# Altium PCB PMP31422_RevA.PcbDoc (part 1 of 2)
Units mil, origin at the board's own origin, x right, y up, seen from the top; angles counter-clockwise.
Board outline 5850 x 1977.34 mil, 2 copper layers (Top Layer, Bottom Layer), stack 62 mil thick; 70 components, 36 nets, 149 pads, 18 vias.
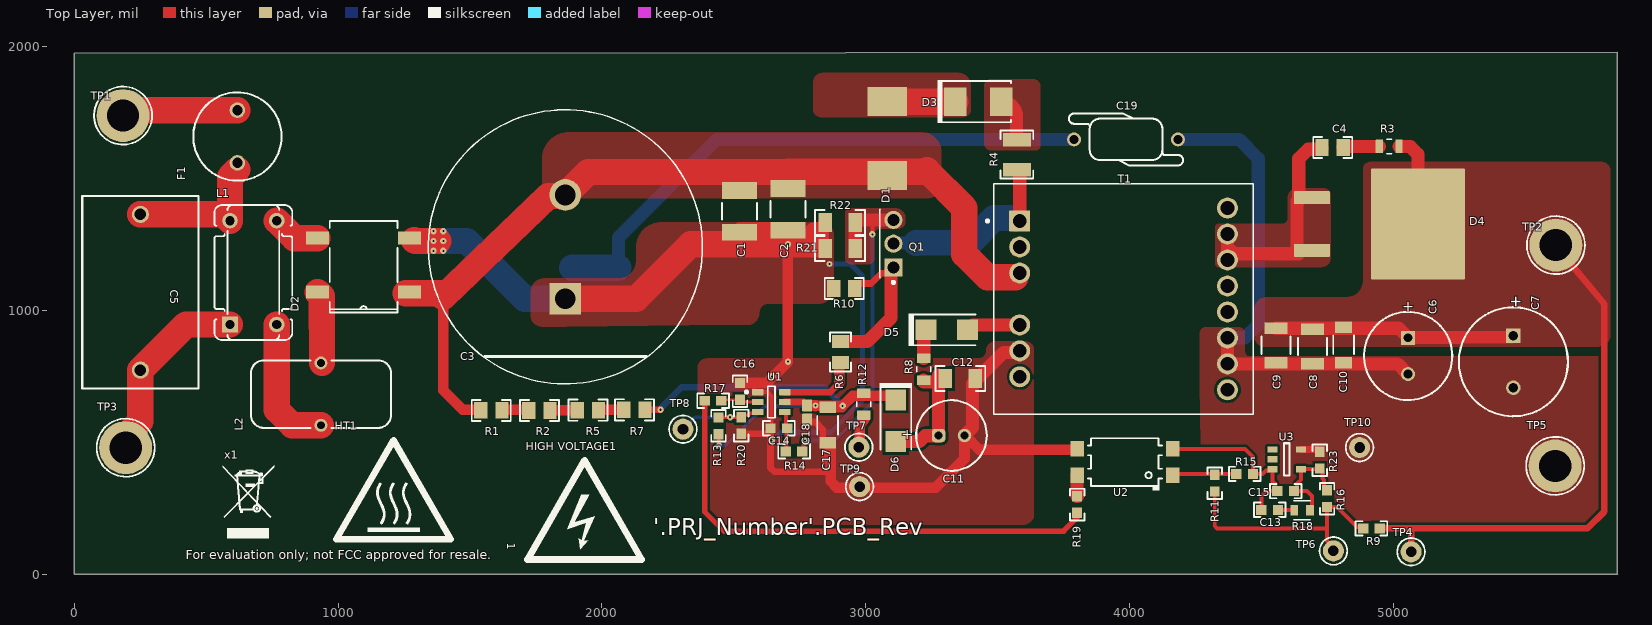
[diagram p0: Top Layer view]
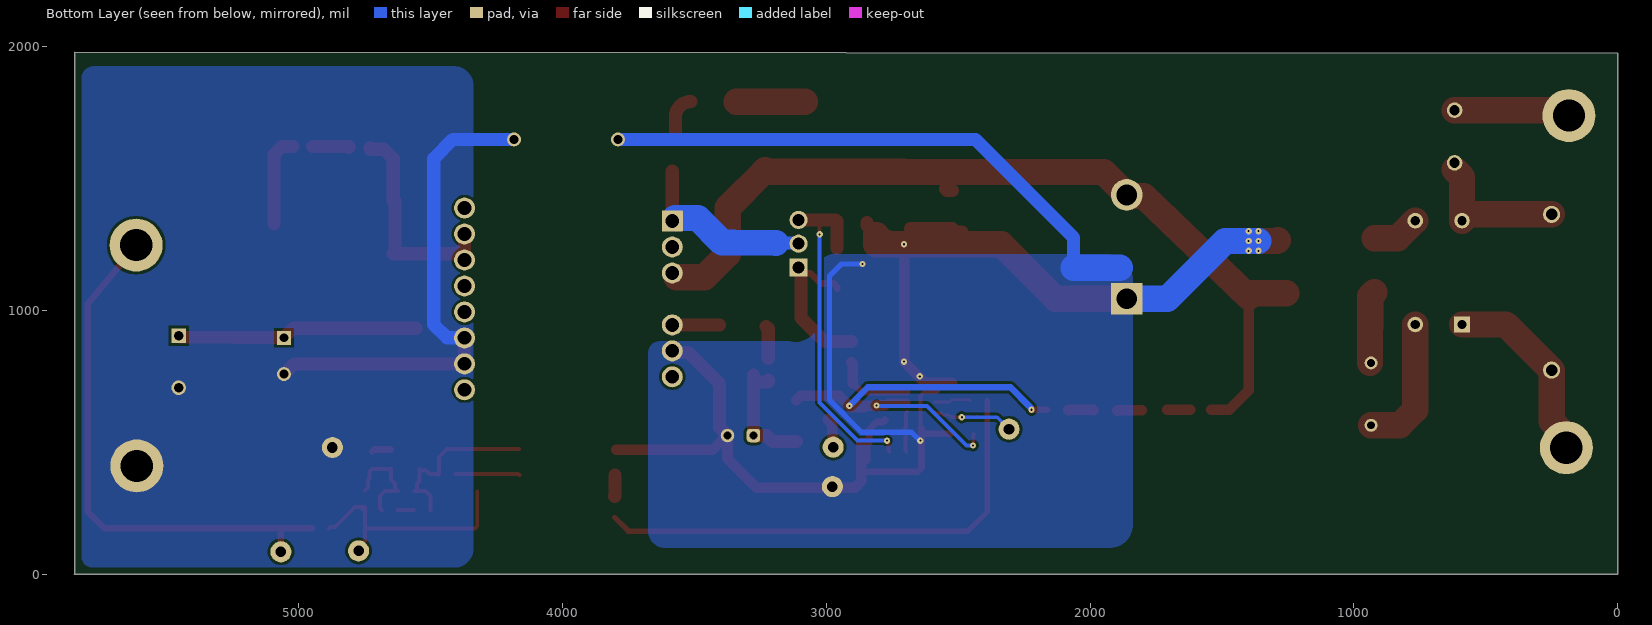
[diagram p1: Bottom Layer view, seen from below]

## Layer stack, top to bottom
Top Solder: solder mask 0.4, Solder Resist, Dk 3.5
Top Layer: signal copper 1.4
Dielectric1: core 59.2, FR-4 High Tg, Dk 4.8
Bottom Layer: signal copper 1.4
Bottom Solder: solder mask 0.4, Solder Resist, Dk 3.5

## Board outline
0,0 5850,0 5847.86,0.02 5847.86,1977.34 0,1975

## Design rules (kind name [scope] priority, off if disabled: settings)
AcuteAngle [All] p1: minimum=4.50000000000000E+0001 checktracksonly=FALSE
AssemblyTestPointUsage [All] p1: valid=2
BoardOutlineClearance BoardOutlineClearance_MountingHoles [OnCopper and InComponentClass('Mounting Holes')] p1: gap=39.37 ignorepadtopadclearanceinfootprint=FALSE
BoardOutlineClearance BoardOutlineClearance_Poly [OnCopper and IsPoly] p2: gap=25 ignorepadtopadclearanceinfootprint=FALSE
BoardOutlineClearance [OnCopper and Not InComponentClass('Logo') and not InComponentClass('FiducialMark') and not InRegion(1000,500,4000,800) and not InPoly] p3: gap=35 ignorepadtopadclearanceinfootprint=FALSE
Clearance Clearance_Keepouts [((IsTrack Or IsArc) And Not InPoly) And IsFree and IsKeepOut vs ((IsTrack Or IsArc) And Not InPoly) And IsFree and IsKeepOut] p1: gap=0 ignorepadtopadclearanceinfootprint=FALSE
Clearance Clearance_Poly [InPolygon] p2: gap=10 ignorepadtopadclearanceinfootprint=TRUE
Clearance Clearance_FiducialMark [IsKeepOut and InComponentClass('FiducialMark') vs IsPad and InComponentClass('FiducialMark')] p3: gap=0 ignorepadtopadclearanceinfootprint=FALSE
Clearance [All] p4: gap=7.87 ignorepadtopadclearanceinfootprint=TRUE
ComponentClearance ComponentClearance_MountingHoles_FiducialMarks [InComponentClass('Mounting Holes') vs InComponentClass('FiducialMark')] p1: gap=50 collisioncheckmode=3 verticalgap=10 showdistances=FALSE
ComponentClearance ComponentClearance_Shunt [InComponentClass('Header') vs InComponentClass('Shunt')] p2: gap=0 collisioncheckmode=3 verticalgap=0 showdistances=FALSE
ComponentClearance ComponentClearance_Logo [InComponentClass('Logo')] p3: gap=30 collisioncheckmode=3 verticalgap=10 showdistances=FALSE
ComponentClearance ComponentClearance_ScrewToNut [(HasFootprint('NY PMS 440 0025 PH')) vs (HasFootprint('Keystone_1902C'))] p4: gap=5 collisioncheckmode=3 verticalgap=10 showdistances=FALSE
ComponentClearance ComponentClearance_MountingHoles [InComponentClass('Mounting Holes')] p5: gap=100 collisioncheckmode=3 verticalgap=100000 showdistances=FALSE
ComponentClearance ComponentClearance_SmallPassives [HasFootprint('0201*') or HasFootprint('0402*') or HasFootprint('0508') or HasFootprint('0603*') or HasFootprint('0612') or HasFootprint('0805*') or HasFootprint('0815*') or HasFootprint('0830*') or HasFootprint('1206*') or HasFootprint('1210*') or HasFootprint('1808*') or HasFootprint('1812*') or HasFootprint('1825*') or HasFootprint('2010*') or HasFootprint('2220*') or HasFootprint('2225*') or HasFootprint('2512*') or HasFootprint('2728*') or HasFootprint('3518*') vs HasFootprint('0201*') or HasFootprint('0402*') or HasFootprint('0508') or HasFootprint('0603*') or HasFootprint('0612') or HasFootprint('0805*') or HasFootprint('0815*') or HasFootprint('0830*') or HasFootprint('1206*') or HasFootprint('1210*') or HasFootprint('1808*') or HasFootprint('1812*') or HasFootprint('1825*') or HasFootprint('2010*') or HasFootprint('2220*') or HasFootprint('2225*') or HasFootprint('2512*') or HasFootprint('2728*') or HasFootprint('3518*')] p6: gap=14.96 collisioncheckmode=3 verticalgap=10 showdistances=FALSE
ComponentClearance ComponentClearance_THtoSMT [IsThruComponent vs IsSMTComponent] p7: gap=30 collisioncheckmode=3 verticalgap=30 showdistances=FALSE
ComponentClearance ComponentClearance_THtoTH [IsThruComponent vs IsThruComponent] p8: gap=20 collisioncheckmode=3 verticalgap=30 showdistances=FALSE
ComponentClearance [All] p9: gap=20 collisioncheckmode=3 verticalgap=10 showdistances=FALSE
DiffPairsRouting [All] p1: maxlimit=100 minlimit=10 mostfreqgap=10 toplayer_minwidth=15 toplayer_maxwidth=15 toplayer_prefwidth=15 bottomlayer_minwidth=15 bottomlayer_maxwidth=15 bottomlayer_prefwidth=15 maxuncoupledlength=1000
FabricationTestPointUsage TestPointUsage [All] p1: valid=2 allowmultiple=FALSE
FabricationTestpoint Testpoint [All] p1: side=3 testpointundercomponent=TRUE minsize=40 maxsize=100 preferedsize=60 minholesize=0 maxholesize=40 preferedholesize=32 testpointgrid=1 allowsidetop=TRUE allowsidebottom=TRUE usegrid=TRUE gridtolerance=0.01
FanoutControl Fanout_LCC [IsLCC] p1: bgadir=Out bgaviamode=Centered fanoutstyle=Auto fanoutdirection=Alternating viagrid=1 // Fanout_LCC (Default Rule)
FanoutControl Fanout_BGA [IsBGA] p2: bgadir=Out bgaviamode=Centered fanoutstyle=Auto fanoutdirection=Alternating viagrid=1 // Fanout_BGA (Default Rule)
FanoutControl Fanout_Default [All] p4: bgadir=Out bgaviamode=Centered fanoutstyle=Auto fanoutdirection=Alternating viagrid=1 // Fanout_Default (Default Rule)
FanoutControl Fanout_Small [(CompPinCount < 5)] p5: bgadir=Out bgaviamode=Centered fanoutstyle=Auto fanoutdirection=OutThenIn viagrid=1 // Fanout_Small (Default Rule)
Height [All] p1: minheight=0 maxheight=1500 prefheight=500
HoleSize [All] p1: absolutevalues=TRUE maxlimit=251 minlimit=7.87 maxpercent=80.000 minpercent=20.000
MinimumAnnularRing MinimumAnnularRing_ThermalPadVias [IsVia and InAnyComponent] p1: minimumring=5.91
MinimumAnnularRing [All] p2: minimumring=7.87
MinimumSolderMaskSliver MinimumSolderMaskSliver_Logo [InComponentClass('Logo') vs InComponentClass('Logo')] p1: minsoldermaskwidth=0.7
MinimumSolderMaskSliver [All] p2: minsoldermaskwidth=3.94
PlaneConnect [All] p1: planeconnectstyle=Relief reliefexpansion=10 reliefentries=4 reliefconductorwidth=10 reliefairgap=10
PolygonConnect [All] p1: connectstyle=Direct reliefconductorwidth=10 reliefentries=4 polygonreliefangle="90 Angle" airgapwidth=10
RoutingVias ThermalPadVias [IsVia and InAnyComponent] p1: holewidth=7.87 width=19.68 viastyle="Through Hole" minholewidth=7.87 minwidth=19.68 maxholewidth=12.99 maxwidth=23.62
RoutingVias [All] p2: holewidth=16 width=34 viastyle="Through Hole" minholewidth=7.87 minwidth=24 maxholewidth=40 maxwidth=65
SilkToBoardRegionClearance [Not ((IsComment or IsDesignator) And (Hide <> 'False')) and not InRegion(1000,500,4000,800)] p1:
SilkToSilkClearance SilkToSilkClearance_Pb-FreeLogo [(HasFootprint('Pb-Free_Overlay_Medium') OR HasFootprint('Pb-Free_Overlay_Small')) vs (HasFootprint('Pb-Free_Overlay_Medium') OR HasFootprint('Pb-Free_Overlay_Small'))] p1 off: silktosilkclearance=0
SilkToSilkClearance [All] p2 off: silktosilkclearance=3.94
SilkToSolderMaskClearance SilkToComponentPadClearance [(IsPad or IsFill or IsRegion) and InAnycomponent] p1 off: minsilkscreentomaskgap=5 clearancetoexposedcopper=TRUE
SilkToSolderMaskClearance "Silk to Solder Mask Opening" [All] p2 off: minsilkscreentomaskgap=3.94 clearancetoexposedcopper=FALSE
SolderMaskExpansion [All] p1: expansion=1.97 istentingtop=FALSE
UnRoutedNet [All] p1: checkbadconnections=TRUE
Width [All] p1: maxlimit=100 minlimit=6 preferedwidth=10 checkconnectedcopper=TRUE
13 further rules are at their usual default settings.

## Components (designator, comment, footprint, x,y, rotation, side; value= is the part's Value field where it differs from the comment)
1 "FCC disclaimer" FCC_disclaimer 1049.65,56.66 r0 top
C1 "1812Y5000474KXTWS2" 1812_254 2521.46,1375.09 r270 top value=0.47uF
C2 "1812Y5000474KXTWS2" 1812_254 2704.98,1382.55 r270 top value=0.47uF
C3 "B43541B8476M080" FP-B43541B8476M080_RADIAL-MFG 1861.1,1240.23 r90 top value=47µF
C4 "GRM2165C2A102JA01D" 0805_HV 4770.03,1617 r180 top value=DNP
C5 "R474I310050A1K" Kemet_1800x1100x1900 250.24,1068.16 r270 top value=0.1uF
C6 "APSG160ELL471MH08S" PSG_800x800 5055.86,826.67 r270 top value=470uF
C7 "16SEPC470M+T" SEPC_F13 5454.97,804.61 r270 top value=470uF
C8 "C3225X7R1C226K250AC" 1210_280 4693.07,862.64 r270 top value=22uF
C9 "C3225X7R1C226K250AC" 1210_280 4555.57,866.49 r270 top value=22uF
C10 "C3216X7R1C106M160AC" 1206_180 4811.17,868.58 r270 top value=10uF
C11 "860040573004" WCAP-ATUL_D6.3H11 3325.01,525.09 r180 top
C12 "GMK316AB7106KL" 1206 3358.13,740.92 r180 top value=10uF
C13 "DNPC0603C220J5GACTU" 0603 4531.38,243.36 r0 top value=DNP
C14 "C0603C220J5GACTU" 0603 2670.46,552.48 r180 top value=22pF
C15 "GRM188R71H103KA01D" 0603 4591.75,314.18 r0 top value=0.01uF
C16 "GRM188R71H102KA01D" 0603 2523.18,692.73 r90 top value=1000pF
C17 "GRM31CR71H475KA12L" 1206_180 2855.32,564.56 r270 top value=4.7uF
C18 "C0603R104K5RAC" FP-C0603R104K5RAC_0603-IPC_B 2777.74,612.5 r270 top
C19 "C901U102MYVDBA7317" C901_B 3986.6,1647.53 r180 top value=1000pF
D1 "SMCJ154CA-TR" SMC_Bi 3081.3,1650.77 r270 top value=154V
D2 "DF08SA" DF-S 1096.11,1171.08 r180 top value=800V
D3 "MURS160-13-F" SMB 3425.98,1790.97 r0 top value=600V
D4 "STPS8H100G-TR" DDPAK 4937.73,1326.93 r0 top value=100V
D5 "B1100-13-F" SMA 3306.68,925.68 r0 top value=100V
D6 "B1100-13-F" SMA 3113.93,580.85 r270 top value=100V
F1 "DNP" FUSE_372 618.02,1658.38 r90 top
"HIGH VOLTAGE1" "DANGER HIGH VOLTAGE" IEC_HighVoltage_Medium 1934.1,230.43 r0 top
HT1 "CAUTION HOT SURFACE" IEC_HotSurface_Medium 1209.94,319.49 r0 top
L1 "744821150" WE-CMB_XS 678.33,1142.82 r90 top value=5mH
L2 "7447031" WE-FI_1350x700 934.52,682 r90 top value=140uH
Q1 "IPSA70R2K0CE" FP-IPSA70R2K0CE_TO251-3-MFG 3099.72,1252.33 r180 top
R1 "CRCW080510M0JNEA" 0805_HV 1580.33,620.15 r180 top value=10Meg
R2 "CRCW080510M0JNEA" 0805_HV 1762.63,620.03 r180 top value=10Meg
R3 "TNPW0805100RBYEN" FP-TNPW0805100RBYEN_0805-MFG 4984.2,1621.14 r0 top value=DNP
R4 "CRCW121010R0FKEAHP" 1210 3573.02,1590.07 r90 top value=10.0
R5 "CRCW080510M0JNEA" 0805_HV 1946.51,621.32 r180 top value=10Meg
R6 "CRCW080510R0FKEA" 0805_HV 2904.09,841.95 r90 top value=10.0
R7 "CRCW080510M0JNEA" 0805_HV 2122.77,622.5 r180 top value=10Meg
R8 "RMCF0805ZT0R00" FP-RMCF0805ZT0R00_0805-MFG 3219.37,776 r90 top
R9 "CRCW060349R9FKEA" 0603 4916.7,172.82 r0 top value=49.9
R10 "CRCW080510K0FKEA" 0805_HV 2918.41,1082.52 r0 top value=10.0k
R11 "RC0603FR-076K49L" 0603 4322.88,344.38 r90 top value=6.49k
R12 "RMCF0805ZT0R00" FP-RMCF0805ZT0R00_0805-MFG 2992.26,643.88 r90 top
R13 "CRCW0603200KFKEA" 0603 2441.65,562.02 r270 top value=200k
R14 "RMCF0603ZT0R00" 0603 2728.14,465.04 r180 top value=0
R15 "RCG060310K0FKEA" 0603 4436.32,379.35 r180 top value=10.0k
R16 "CRCW06031M00FKEA" 0603 4748.71,285.44 r270 top value=1.00Meg
R17 "RMCF0603ZT0R00" 0603 2421.11,656.71 r180 top value=0
R18 "DNP" FP-CRCW06030000Z0EAHP_0603-MFG 4654.19,241.57 r0 top
R19 "RMCF0603ZT0R00" 0603 3801.39,263.28 r270 top value=0
R20 "CRCW060368K1FKEA" 0603 2528.08,562.7 r90 top value=68.1k
R21 "TBD" 1206 2902.58,1234.09 r0 top
R22 "ERJ-8RQF1R8V" 1206 2902.54,1332.97 r0 top value=1.80
R23 "CRCW0603115KFKEA" 0603 4720.83,431.5 r90 top value=115k
T1 "750372566r00" FP-750372566r00_PTH14-MFG 3977.31,1042.78 r0 top
TP1 "1503-2" Keystone1503-2 184.35,1737.92 r90 top
TP2 "1503-2" Keystone1503-2 5615.95,1246.72 r90 top
TP3 "1503-2" Keystone1503-2 194.5,478.89 r0 top
TP4 "5000" Keystone5000 5067.09,84.27 r90 top
TP5 "1503-2" Keystone1503-2 5613.53,410.04 r0 top
TP6 "5000" Keystone5000 4772.83,87.67 r90 top
TP7 "5000" Keystone5000 2973.59,480.76 r90 top
TP8 "5000" Keystone5000 2307,548.99 r90 top
TP9 "5002" Keystone5002 2976.44,331.41 r90 top
TP10 "5001" Keystone5001 4871.84,479.56 r90 top
U1 "UCC287508DBVR" DBV0006A-MFG 2641.97,652.07 r0 top
U2 "FOD817ASD" N04C 3982.37,424.56 r180 top
U3 "TLV431AIDBVT" DBV0005A_N 4595.95,434.74 r0 top
x1 "WEEE logo" WEEE_Minimum 657.54,307.2 r0 top

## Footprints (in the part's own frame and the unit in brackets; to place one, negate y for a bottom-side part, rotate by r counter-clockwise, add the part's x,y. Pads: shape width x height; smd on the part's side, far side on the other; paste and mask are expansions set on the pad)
0603 [mm] "0603 from SM-752 data"
  rect 1x0.95 smd: 1(-0.8,0) 2(0.8,0)
  silkscreen extent -1.52,-0.69 1.52,0.69, body extent -0.87,-0.47 0.87,0.47, height 1
0805_HV [mil] "0805 with 30mil clearance between pads"
  rect 50x63 smd: 1(-40,0) 2(40,0)
  silkscreen extent -74,-40 74,40, body extent -43,-29 43,29, height 57
1206 [mm] "1206 from SM-752 data"
  rect 1.3x1.85 smd: 1(-1.45,0) 2(1.45,0)
  silkscreen extent -2.4,-1.21 2.4,1.21, body extent -1.7,-0.9 1.7,0.9, height 1.35
1206_180 [mm] "1206_180"
  rect 1.1x1.6 smd: 1(-1.7,0) 2(1.7,0)
  silkscreen extent -0.9,-1 0.9,1, body extent -1.75,-0.95 1.75,0.95, height 1.8
1210 [mm] "1210 from SM-752 data"
  rect 1.3x2.7 smd: 1(-1.45,0) 2(1.45,0)
  silkscreen extent -2.32,-1.57 2.32,1.57, body extent -1.7,-1.35 1.7,1.35, height 1.35
1210_280 [mm] "SMD, 2-Leads, Body 3.6x2.8mm, Height 2.8mm"
  rect 1.1x2.2 smd: 1(-1.65,0) 2(1.65,0)
  silkscreen extent -0.84,-1.4 0.84,1.4, body extent -1.8,-1.4 1.8,1.4, height 2.8
1812_254 [mm] "SMD, 2-Leads, Body 4.8x3.4mm"
  rect 1.6x3.4 smd: 1(-2,0) 2(2,0)
  silkscreen extent -0.8,-1.7 0.8,1.7, body extent -2.4,-1.7 2.4,1.7, height 2.54
C901_B [mm] "TH, 2-Leads, Body 7x5mm, Pin Spacing 10mm"
  round 1.35 hole 0.85: 1(-5,0) 2(5,0)
  silkscreen extent -5.5,-2.5 5.5,2.5, body extent -5.5,-2.5 5.5,2.5, height 11
DBV0005A_N [mm] "SOT23, 5-Leads, Body 2.9x1.6mm, Pitch 0.95mm, Lead Span 2.8mm, IPC Medium Density"
  rrect17% 1x0.6 smd: 1(-1.375,0.95) 2(-1.375,0) 3(-1.375,-0.95) 4(1.375,-0.95) 5(1.375,0.95)
  silkscreen extent -0.25,-1.55 0.25,1.55, body extent -1.42,-1.46 1.42,1.46, height 1.09
DBV0006A-MFG [mm]
  rrect17% 1.1x0.6 smd paste+0 mask+0: 1(-1.3,0.95) 2(-1.3,0) 3(-1.3,-0.95) 4(1.3,-0.95) 5(1.3,0) 6(1.3,0.95)
  silkscreen extent -2.52,-1.53 0.35,1.53, body extent -1.95,-1.78 1.95,1.78, height 0.25
DDPAK [mil] "D2-PAK, 3-Pads, Body 9.7x10.4mm (max), TO-263AB, using Vishay Silionix recommended pad sizes"
  rrect8% 135x49.49 smd: 1(-246.06,100) 3(-246.06,-100)
  rrect1% 355x420 smd paste-181.1: 2(155.51,0)
  body extent -295,-202 324,202, height 180
DF-S [mil] "Diodes Inc. recommended land pattern per ap02001.pdf rev 30"
  rect 88x49 smd: 1(-174.5,102.36) 2(-174.5,-102.36) 3(174.5,-102.36) 4(174.5,102.36)
  silkscreen extent -128,-168 128,180, body extent -205,-168 205,168, height 108
FCC_disclaimer [mil]
FP-750372566r00_PTH14-MFG [mm] "Recommended Land Pattern"
  rrect5% 2.02x2.02 hole 1.32 paste-2539.97 mask+0: 1(-10,7.5)
  round 2.02 hole 1.32 paste-2539.97 mask+0: 2(-10,5) 3(-10,2.5) 4(-10,-2.5) 5(-10,-5) 6(-10,-7.5) 7(10,-8.75) 8(10,-6.25) 9(10,-3.75) 10(10,-1.25) 11(10,1.25) 12(10,3.75) 13(10,6.25) 14(10,8.75)
  silkscreen extent -13.22,-11.1 12.5,11.1, body extent -12.5,-11.1 12.5,11.1, height 16
FP-B43541B8476M080_RADIAL-MFG [mm] "Recommended Land Pattern"
  rrect3% 3.05x3.05 hole 2 paste-2539.97 mask+0: 1(-5,0)
  round 3.05 hole 2 paste-2539.97 mask+0: 2(5,0)
  silkscreen extent -13.2,-13.2 13.2,13.2, body extent -12.5,-12.5 12.5,12.5, height 27.2
FP-C0603R104K5RAC_0603-IPC_B [mil]
  rrect10% 44.33x37.73 smd paste+0 mask+0: 1(-26.6,0) 2(26.6,0)
  body extent -59,-29 59,29, height 10
FP-CRCW06030000Z0EAHP_0603-MFG [mm]
  rrect13% 0.75x1 smd paste+0 mask+0: 1(-0.75,0) 2(0.75,0)
  silkscreen extent -0.8,-0.9 0.8,0.9, body extent -1.22,-0.6 1.22,0.6, height 0.25
FP-IPSA70R2K0CE_TO251-3-MFG [mm] "Recommended Land Pattern"
  rrect6% 1.75x1.75 hole 1.15 paste-2539.97 mask+0: 1(-0.128,2.286)
  round 1.75 hole 1.15 paste-2539.97 mask+0: 2(-0.128,0) 3(-0.128,-2.286)
  silkscreen extent -0.25,-3.3 1.19,3.85, body extent -1.15,-3.3 1.15,3.3, height 9
FP-RMCF0805ZT0R00_0805-MFG [mm]
  rrect11% 0.9x1.3 smd paste+0 mask+0: 1(-1.05,0) 2(1.05,0)
  silkscreen extent -0.23,-0.67 0.23,0.67, body extent -1.6,-0.77 1.6,0.77, height 0.25
FP-TNPW0805100RBYEN_0805-MFG [mm]
  rrect14% 0.7x1.3 smd paste+0 mask+0: 1(-0.95,0) 2(0.95,0)
  silkscreen extent -0.23,-0.7 0.23,0.7, body extent -1.4,-0.8 1.4,0.8, height 0.25
FUSE_372 [mm] "LITTELFUSE"
  round 1.5 hole 1: 1(-2.54,0) 2(2.54,0)
  silkscreen extent -4.25,-4.25 4.25,4.25, body extent -4.25,-4.25 4.25,4.25, height 8
IEC_HighVoltage_Medium [mil]
  silkscreen extent -217,-176 217,200
IEC_HotSurface_Medium [mil]
  silkscreen extent -217,-188 217,188
Kemet_1800x1100x1900 [mm] "TH, 2-Leads, Body 18x11mm, Pin Spacing 15mm"
  round 1.65 hole 1.1: 1(-7.5,0) 2(7.5,0)
  silkscreen extent -9.25,-5.6 9.25,5.6, body extent -9.25,-5.6 9.25,5.6, height 19.1
Keystone1503-2 [mm] "Double Turret"
  round 5.1 hole 3.1: 1(0,0)
  silkscreen extent -2.79,-2.79 2.79,2.79, body extent -2.4,-2.4 2.38,2.4, height 9.22
Keystone5000 [mil] "For Keystone 500x miniature loop terminals"
  round 80 hole 40: 1(0,0)
  silkscreen extent -52,-52 52,52, body extent -49,-49 49,49, height 182
Keystone5001 [mil] "For Keystone 500x miniature loop terminals"
  round 80 hole 40: 1(0,0)
  silkscreen extent -52,-52 52,52, body extent -49,-49 49,49, height 182
Keystone5002 [mil] "For Keystone 500x miniature loop terminals"
  round 80 hole 40: 1(0,0)
  silkscreen extent -52,-52 52,52, body extent -49,-49 49,49, height 182
N04C [mm] "FAIRCHILD"
  rect 1.3x1.5 smd mask+0.065: 1(-4.587,1.27) 2(-4.612,-1.27) 3(4.588,-1.27) 4(4.613,1.27)
  silkscreen extent -3.56,-2.3 3.56,2.72, body extent -5.08,-2.3 5.08,2.3, height 3.87
PSG_800x800 [mm] "TH, 2-Leads, Dia 8mm, Pin Spacing 3.5mm"
  rect 1.35x1.35 hole 0.85: 1(-1.75,0)
  round 1.35 hole 0.85: 2(1.75,0)
  silkscreen extent -4.25,-4.25 4.25,4.25, body extent -4.25,-4.25 4.25,4.25, height 9.01
SEPC_F13 [mm] "TH, 2-Leads, Dia 10mm, Pin Spacing 5mm"
  rect 1.4x1.4 hole 0.9: 1(-2.5,0)
  round 1.4 hole 0.9: 2(2.5,0)
  silkscreen extent -5.25,-5.25 5.25,5.25, body extent -5.25,-5.25 5.25,5.25, height 13.01
SMA [mm] "Molded Diode, 2-Leads, Body 4.3x2.6mm, IPC Medium Density, based on OnSemi component dimensions and land pattern"
  rect 2x2 smd: 1(-2,0) 2(2,0)
  silkscreen extent -3.66,-1.57 2.79,1.57, body extent -2.6,-1.3 2.6,1.3, height 2.42
SMB [mil] "Molded Diode, 2-Leads, Body 5.4x3.6mm, IPC Medium Density, based on OnSemi component dimensions"
  rect 85x107.99 smd: 1(-87.01,0) 2(87.01,0)
  silkscreen extent -155,-82 125,82, body extent -106,-71 106,71, height 91
SMC_Bi [mil] "SMC, no polarity mark"
  rect 110x150 smd: 1(-140.49,0) 2(140.49,0)
  body extent -156,-116 156,116, height 92
WCAP-ATUL_D6.3H11 [mm] "Aluminum Electrolytic Capacitors, 6.3x11mm"
  rrect50% 1.3x1.3 hole 0.8: 1(1.25,0)
  round 1.3 hole 0.8: 2(-1.25,0)
  silkscreen extent -3.4,-3.4 3.4,3.4, body extent -3.14,-3.15 3.15,3.15, height 11.31
WE-CMB_XS [mm] "WE-CMB Series Size XS"
  rect 1.5x1.5 hole 0.9: 1(-5,2.25)
  round 1.5 hole 0.9: 2(-5,-2.25) 3(5,-2.25) 4(5,2.25)
  silkscreen extent -6.5,-3.75 6.5,3.75, body extent -6.5,-3.75 6.5,3.75, height 16.24
WE-FI_1350x700 [mm] "TH, 2-Leads, Dia 13.5mm"
  round 1.25 hole 0.75: 1(-3,0) 2(3,0)
  silkscreen extent -3.25,-6.75 3.25,6.75, body extent -3.25,-6.75 3.25,6.75, height 13.32
WEEE_Minimum [mil] "WEEElie bin"
  silkscreen extent -95,-172 99,104

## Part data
1: library part CMP-0074847-1, "FCC_disclaimer"
C1 C2: library part CMP-0009298-2, "DNP", Cap_Case=1812, Manufacturer="Knowles Capacitors", Supplier Part Number 1=1608-1155-1-ND, TempCo=X7R, Tolerance_%=10%, Value1=Unknown, Value2=500V
C3: library part CMP-0127623-1, "47 µF 600 V Aluminum Electrolytic Capacitors Radial, Can - Snap-In 2.47Ohm @ 100Hz 5000 Hrs @ 85°C", Digikey Part Number=495-B43541B8476M080-ND, Leakage Current=400uA, Manufacturer=TDK, Mouser Part Number=871-B43541B8476M80, Operating Temperature Range="-25°C to +85°C", Tolerance_%=20%, ValueDisplayed=47uF
C4: library part CMP-0008094-2, "DNP", Cap_Case=0805, Manufacturer=MuRata, TempCo=C0G/NP0, Tolerance_%=5%, Value1=Unknown
C5: library part CMP-0074799-2, "CAP, Film, 0.1 µF, X1 440 VAC, +/- 10%, AEC-Q200 Grade 1, TH", Cap_Case=18x11x19mm, Manufacturer=Kemet, Supplier Part Number 1=399-12721-ND, Tolerance_%=10%, Value2=1000V, ValueDisplayed=0.1µF
C6: library part CMP-0012172-1, "CAP, Aluminum Polymer, 470 uF, 16 V, +/- 20%, 0.016 ohm, TH", Cap_Case=8x8mm, Manufacturer=Chemi-Con, Supplier Part Number 1=565-3620-ND, Tolerance_%=20%, Value1="0.016 ohm", Value2=16V, ValueDisplayed=470uF
C7: library part CMP-0012077-2, "CAP, Aluminum Polymer, 470 uF, 16 V, +/- 20%, 0.01 ohm, TH", Cap_Case=10x13mm, Manufacturer=Panasonic, Supplier Part Number 1=P16383CT-ND, Tolerance_%=20%, Value1="0.01 ohm", Value2=16V, ValueDisplayed=470uF
C8 C9: library part CMP-0009116-1, "CAP, CERM, 22 uF, 16 V, +/- 10%, X7R, 1210", Cap_Case=1210_280, Manufacturer=TDK, Supplier Part Number 1=445-3945-1-ND, TempCo=X7R, Tolerance_%=10%, Value1="0.002582 ohm", Value2=16V, ValueDisplayed=22uF
C10: library part CMP-0082521-1, "CAP, CERM, 10 µF, 16 V,+/- 20%, X7R, 1206", Cap_Case=1206, Manufacturer=TDK, Supplier Part Number 1=445-1601-1-ND, TempCo=X7R, Tolerance_%=20%, Value2=16V, ValueDisplayed=10µF
C11: library part CMP-0116855-1, "WCAP-ATUL Aluminum Electrolytic Capacitor, Radial, THT, D6.3 x H11mm, 100µF, 35V", Capacitance Tolerance=20%, Leakage Current=35uA, Manufacturer="Wurth Elektronik", Operating Temperature Max=105°C, Operating Temperature Min=-40°C, Rated Voltage (DC)=35V, Ripple Current=450mA
C12: library part CMP-0008821-1, "CAP, CERM, 10 uF, 35 V, +/- 10%, X7R, 1206", Cap_Case=1206, Manufacturer="Taiyo Yuden", Supplier Part Number 1=587-3007-1-ND, TempCo=X7R, Tolerance_%=10%, Value1=Unknown, Value2=35V, ValueDisplayed=10uF
C13: library part CMP-0006892-1, "DNP", Cap_Case=0603, Manufacturer=Kemet, Supplier Part Number 1=399-1053-1-ND, TempCo=C0G/NP0, Tolerance_%=5%, Value1=Unknown, Value2=50V
C14: library part CMP-0006892-1, "CAP, CERM, 22 pF, 50 V, +/- 5%, C0G/NP0, 0603", Cap_Case=0603, Manufacturer=Kemet, Supplier Part Number 1=399-1053-1-ND, TempCo=C0G/NP0, Tolerance_%=5%, Value1=Unknown, Value2=50V, ValueDisplayed=22pF
C15: library part CMP-0007433-1, "CAP, CERM, 0.01 uF, 50 V, +/- 10%, X7R, 0603", Cap_Case=0603, Manufacturer=MuRata, Supplier Part Number 1=490-1512-1-ND, TempCo=X7R, Tolerance_%=10%, Value1=Unknown, Value2=50V, ValueDisplayed=0.01uF
C16: library part CMP-0007432-1, "CAP, CERM, 1000 pF, 50 V, +/- 10%, X7R, 0603", Cap_Case=0603, Manufacturer=MuRata, Supplier Part Number 1=490-1494-1-ND, TempCo=X7R, Tolerance_%=10%, Value1=Unknown, Value2=50V, ValueDisplayed=1000pF
C17: library part CMP-0008969-2, "CAP, CERM, 4.7 uF, 50 V, +/- 10%, X7R, 1206", Cap_Case=2220, Manufacturer=MuRata, Supplier Part Number 1=24R6347, TempCo=X7R, Tolerance_%=10%, Value1=Unknown, Value2=50V, ValueDisplayed=4.7uF
C18: library part CMP-0087061-2, "CAP CER 0.1UF 50V X7R 0603", Manufacturer=Kemet, TempCo=15%, Tolerance_%=10%
C19: library part CMP-0009592-2, "CAP, CERM, 1000 pF,  V, +/- 20%, Y5V, D7xT5mm", Cap_Case=7x5mm, Manufacturer=Kemet, Supplier Part Number 1=399-9464-1-ND, TempCo=Y5V, Tolerance_%=20%, Value1=Unknown, Value2=V, ValueDisplayed=1000pF
D1: library part CMP-0085466-1, "Diode, TVS, Bi, 154 V, 246 Vc, 1500 W, 6.1 A, SMC (No Polarity Mark)", Manufacturer=STMicroelectronics, Value1=246V
D2: library part CMP-0029205-3, "Diode, Switching-Bridge, 800 V, 1 A, DF-S", Manufacturer=Vishay-Semiconductor, Value1=1A, Value2=1.1V
D3: library part CMP-0029028-2, "Diode, Ultrafast, 600 V, 1 A, SMB", Manufacturer="Diodes Inc.", Value1=1A, Value2=1.25V
D4: library part CMP-0028896-3, "Diode, Schottky, 100 V, 8 A, DDPAK", Manufacturer=STMicroelectronics, Value1=8A, Value2=0.71V
D5 D6: library part CMP-0028371-2, "Diode, Schottky, 100 V, 1 A, SMA", Manufacturer="Diodes Inc.", Value1=1A, Value2=0.79V
F1: library part CMP-0003555-1, "Fuse, 2 A, 250VAC/VDC, TH", Irating_A=2A, Manufacturer=Littelfuse
"HIGH VOLTAGE1": library part CMP-0074835-1, "IEC 61010-1 High Voltage Warning"
HT1: library part CMP-0074837-1, "IEC 61010-1 Hot Surface Warning"
L1: library part CMP-0084275-1, "Coupled inductor, 5 mH, 0.22 ohm, TH", Manufacturer="Wurth Elektronik", ValueDisplayed=5mH
L2: library part CMP-0064732-2, "Inductor, Toroid, Powdered Iron, 140 uH, 1 A, 0.11 ohm, TH", Manufacturer="Wurth Elektronik", Value1="0.11 ohm", Value2=1A, ValueDisplayed=140uH
Q1: library part CMP-0127653-1, "Trans MOSFET N-CH 700V 4A 3-Pin(3+Tab) TO-251 Tube", Drain To Source Breakdown Voltage=700V, Input Capacitance At Vds="163pF @ 100V", Manufacturer=Infineon, Operating Temperature Range="-40°C to +150°C", Power_W=42W, Pulse Drain Current=6.3A, Typ Forward Diode Voltage=0.9V
R1 R2 R5 R7: library part CMP-0020447-1, "RES, 10 M, 5%, 0.125 W, 0805", Manufacturer=Vishay-Dale, Power_W=125mW, Supplier Part Number 1=541-10MACT-ND, TempCo="200 ppm/C", Tolerance_%=5%, Value2=0.125W, Value_Code=10M0, ValueDisplayed=10M
R3: library part CMP-0091372-1, Digikey Part Number=541-9838-1-ND, Manufacturer=Vishay, Mouser Part Number=71-TNPW0805100RBYEN, Operating Temperature Range="-55°C to +155°C", Power_W=200mW, TempCo=10ppm/°C, Tolerance_%=0.1%
R4: library part CMP-0015019-1, "RES, 10.0, 1%, 0.75 W, AEC-Q200 Grade 0, 1210", Manufacturer=Vishay-Dale, Power_W=750mW, Supplier Part Number 1=541-10.0DCT-ND, TempCo="100 ppm/C", Tolerance_%=1%, Value2=0.75W, Value_Code=10R0, ValueDisplayed=10.0
R6: library part CMP-0020847-3, "RES, 10.0, 1%, 0.125 W, AEC-Q200 Grade 0, 0805", Manufacturer=Vishay-Dale, Power_W=125mW, Supplier Part Number 1=541-10.0CCT-ND, TempCo="100 ppm/C", Tolerance_%=1%, Value2=0.125W, Value_Code=10R0, ValueDisplayed=10.0
R8 R12: library part CMP-0089632-1, "0 Ohms Jumper 0.125W, 1/8W Chip Resistor 0805 (2012 Metric) Automotive AEC-Q200 Thick Film", Digikey Part Number=RMCF0805ZT0R00CT-ND, Manufacturer="Stackpole Electronics", Operating Temperature Range="-55°C to +155°C", Power_W=125mW, TempCo=200ppm/°C
R9: library part CMP-0022448-2, "RES, 49.9, 1%, 0.1 W, 0603", Manufacturer=Vishay-Dale, Power_W=100mW, Supplier Part Number 1=541-49.9HCT-ND, TempCo="100 ppm/C", Tolerance_%=1%, Value2=0.1W, Value_Code=49R9, ValueDisplayed=49.9
R10: library part CMP-0020842-2, "RES, 10.0 k, 1%, 0.125 W, 0805", Manufacturer=Vishay-Dale, Power_W=125mW, Supplier Part Number 1=541-10.0KCCT-ND, TempCo="100 ppm/C", Tolerance_%=1%, Value2=0.125W, Value_Code=10k0, ValueDisplayed=10.0k
R11: library part CMP-0023250-5, "RES, 6.49 k, 1%, 0.1 W, 0603", Manufacturer=Yageo, Power_W=100mW, Supplier Part Number 1=311-6.49KHRCT-ND, TempCo="100 ppm/C", Tolerance_%=1%, Value2=0.1W, Value_Code=6k49, ValueDisplayed=6.49k
R13: library part CMP-0022200-3, "RES, 200 k, 1%, 0.1 W, 0603", Manufacturer=Vishay-Dale, Power_W=100mW, Supplier Part Number 1=541-200KHCT-ND, TempCo="100 ppm/C", Tolerance_%=1%, Value2=0.1W, Value_Code=200k
R14 R17 R19: library part CMP-0023343-2, "RES, 0, 1%, 0.1 W, AEC-Q200 Grade 0, 0603", Manufacturer="Stackpole Electronics Inc", Power_W=100mW, Supplier Part Number 1=RMCF0603ZT0R00CT-ND, TempCo=ppm/C, Tolerance_%=1%, Value2=0.1W, Value_Code=0
R15: library part CMP-0023337-1, "RES, 10.0 k, 1%, 0.1 W, 0603", Manufacturer="Vishay Draloric", Power_W=100mW, Supplier Part Number 1=541-1784-1-ND, TempCo="100 ppm/C", Tolerance_%=1%, Value2=0.1W, Value_Code=10k0, ValueDisplayed=10.0k
R16: library part CMP-0022138-4, "RES, 1.00 M, 1%, 0.1 W, AEC-Q200 Grade 0, 0603", Manufacturer=Vishay-Dale, Power_W=100mW, Supplier Part Number 1=541-1.00MHCT-ND, TempCo="100 ppm/C", Tolerance_%=1%, Value2=0.1W, Value_Code=1M00, ValueDisplayed=1.00M
R18: library part CMP-0122893-1, Manufacturer=Vishay, Operating Temperature Range="-55°C to +155°C", Power=250mW
R20: library part CMP-0022552-3, "RES, 68.1 k, 1%, 0.1 W, 0603", Manufacturer=Vishay-Dale, Power_W=100mW, Supplier Part Number 1=541-68.1KHCT-ND, TempCo="100 ppm/C", Tolerance_%=1%, Value2=0.1W, Value_Code=68k1, ValueDisplayed=68.1k
R21: library part CMP-0017777-2, Manufacturer=Panasonic, PartNumber=DNP, Power_W=250mW, Supplier Part Number 1=P2.2RCT-ND, TempCo="200 ppm/C", Tolerance_%=1%, Value2=0.25W, Value_Code=2R20
R22: library part CMP-0017776-2, "RES, 1.80, 1%, 0.25 W, 1206", Manufacturer=Panasonic, Power_W=250mW, Supplier Part Number 1=P1.8RCT-ND, TempCo="200 ppm/C", Tolerance_%=1%, Value2=0.25W, Value_Code=1R80, ValueDisplayed=1.80
R23: library part CMP-0022012-1, "RES, 115 k, 1%, 0.1 W, 0603", Manufacturer=Vishay-Dale, Power_W=100mW, Supplier Part Number 1=541-115KHCT-ND, TempCo="100 ppm/C", Tolerance_%=1%, Value2=0.1W, Value_Code=115k
T1: library part CMP-0128238-1, "TRANSFORMER", Frequency_Fixed=200kHz, Manufacturer=Wurth, Operating Temperature Range="-40°C to +125°C", Voltage_Isolation_Vrms=3.75kV
TP1 TP2 TP3 TP5: library part CMP-0055114-1, "Terminal, Turret, TH, Double", Manufacturer=Keystone, Supplier Part Number 1=36-1503-2-ND
TP4 TP6 TP7 TP8: library part CMP-0055137-2, "Test Point, Miniature, Red, TH", Color=Red, Manufacturer="Keystone Electronics", Supplier Part Number 1=36-5000-ND
TP9: library part CMP-0055139-1, "Test Point, Miniature, White, TH", Color=White, Manufacturer=Keystone, Supplier Part Number 1=36-5002-ND
TP10: library part CMP-0055138-1, "Test Point, Miniature, Black, TH", Color=Black, Manufacturer=Keystone, Supplier Part Number 1=36-5001-ND
U1: library part CMP-0121343-1, "Current-Mode Flyback Controller with Secondary-Side Regulation (SSR) for Off-Line Applications", Manufacturer="Texas Instruments", Max Supply Voltage=26V, Min Supply Voltage=10V, Nominal Supply Current=2mA, Operating Temperature Range="-40°C to +125°C", Switching Frequency=100kHz
U2: library part CMP-0006181-3, "Optocoupler, 5 kV, 80-160% CTR, SMT", Manufacturer="Fairchild Semiconductor", Supplier Part Number 1=FOD817ASDCT-ND, Voltage_Isolation_Vrms=5kV
U3: library part CMP-0032942-1, "Low Voltage Adjustable Precision Shunt Regulator, 39 ppm / degC, 15 mA, -40 to 85 degC, 5-pin SOT-23 (DBV), Green (RoHS & no Sb/Br)", Manufacturer="Texas Instruments", Rating=Catalog, Temp Coeff(Max)(ppm/ degree C)=129, Temp Coeff(Typ)(ppm/ degree C)=39
x1: library part CMP-0074769-1

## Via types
v1: diameter 24, hole 7.87, Top Layer to Bottom Layer, tented both sides, 10 vias
v2: diameter 24, hole 8, Top Layer to Bottom Layer, tented both sides, 8 vias

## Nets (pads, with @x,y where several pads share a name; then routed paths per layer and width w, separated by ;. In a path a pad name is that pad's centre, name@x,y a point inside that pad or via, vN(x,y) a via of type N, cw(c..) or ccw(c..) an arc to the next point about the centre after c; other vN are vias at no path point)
Bias: C17.1 C18.1 D6.1 R7.1 R12.2 R13.2 U1.5 | length 1789.4
  Top Layer w15: R13.2@2441.65,530.53 2442.66,529.52 2442.66,488 v1(2443.66,486.99)
  Top Layer w25: R7.1@2162.77,622.5 2221.73,622.5 v1(2221.82,622.59) ; U1.5@2693.15,652.07 2764.53,652.07 2776.37,640.24 C18.1@2776.37,636.93
  Top Layer w40: C18.1@2777.74,639.11 v1(2809.57,639.11) ; v1@2808.2,636.93 2808.76,637.5 v1(2912.5,637.5) ; C17.1@2855.32,631.49 2856.97,633.14 2908.14,633.14 v1(2912.5,637.5) ; D6.1@3113.93,659.59 3098.53,675 2950,675 v1(2912.5,637.5)
  Bottom Layer w15: v1(2443.66,486.99) 2467.76,486.99 2617.7,636.93 2801.03,636.93 2801.48,637.38 2807.75,637.38 v1@2808.2,636.93
  Bottom Layer w25: v1@2225,631.49 2301.2,707.68 2842.32,707.68 v1(2912.5,637.5)
FB: R17.2 R19.2 | length 1885.2
  Top Layer w20: R17.2@2389.61,656.71 2389.61,235.39 2462.5,162.5 3750,162.5 R19.2@3801.84,214.34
